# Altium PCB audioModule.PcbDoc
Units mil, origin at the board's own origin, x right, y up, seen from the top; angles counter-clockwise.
Board outline 1259.84 x 708.66 mil, 2 copper layers (Top Layer, Bottom Layer); 25 components, 25 nets, 91 pads, 34 vias.
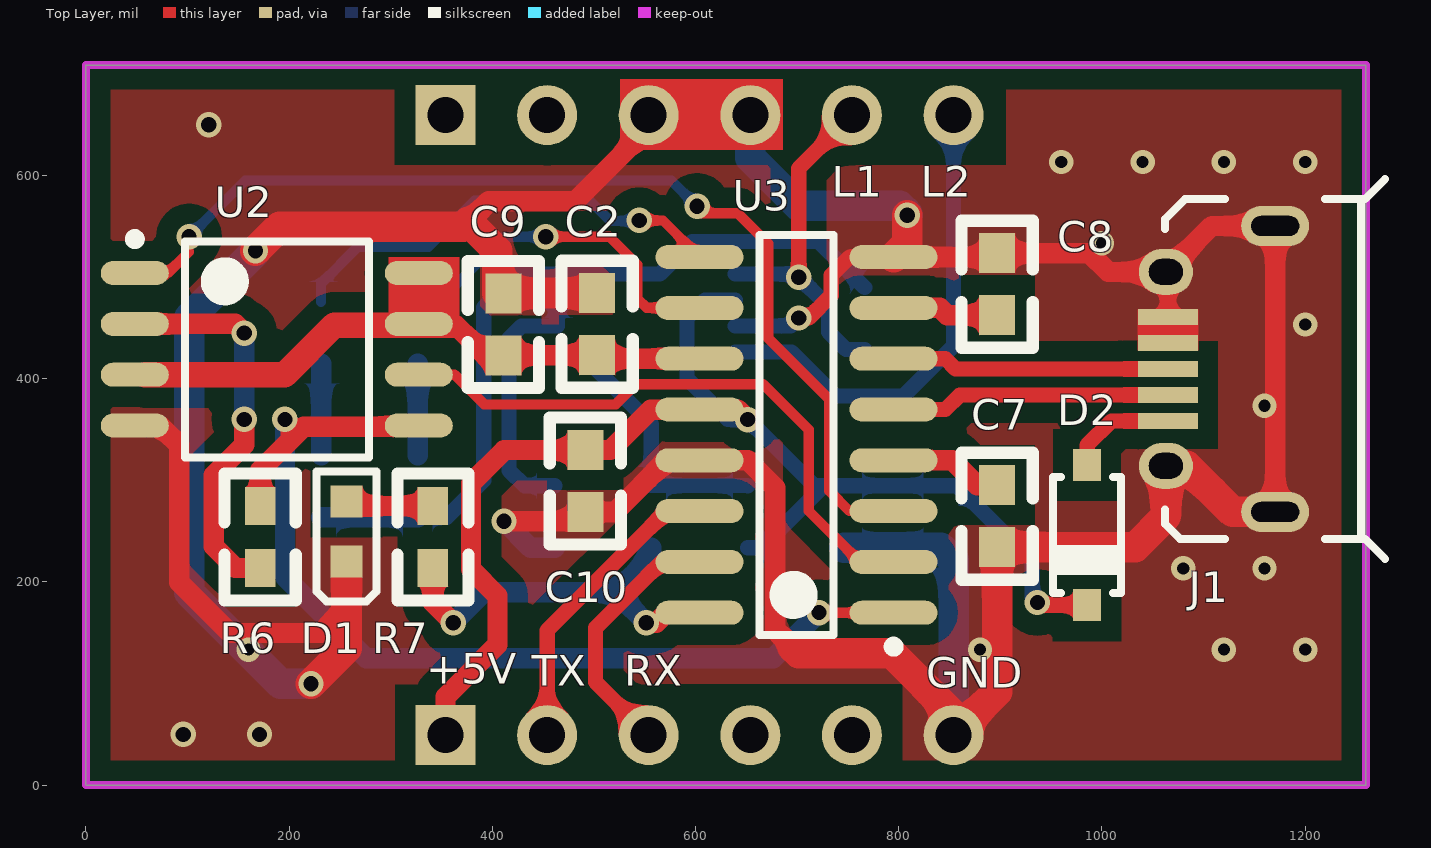
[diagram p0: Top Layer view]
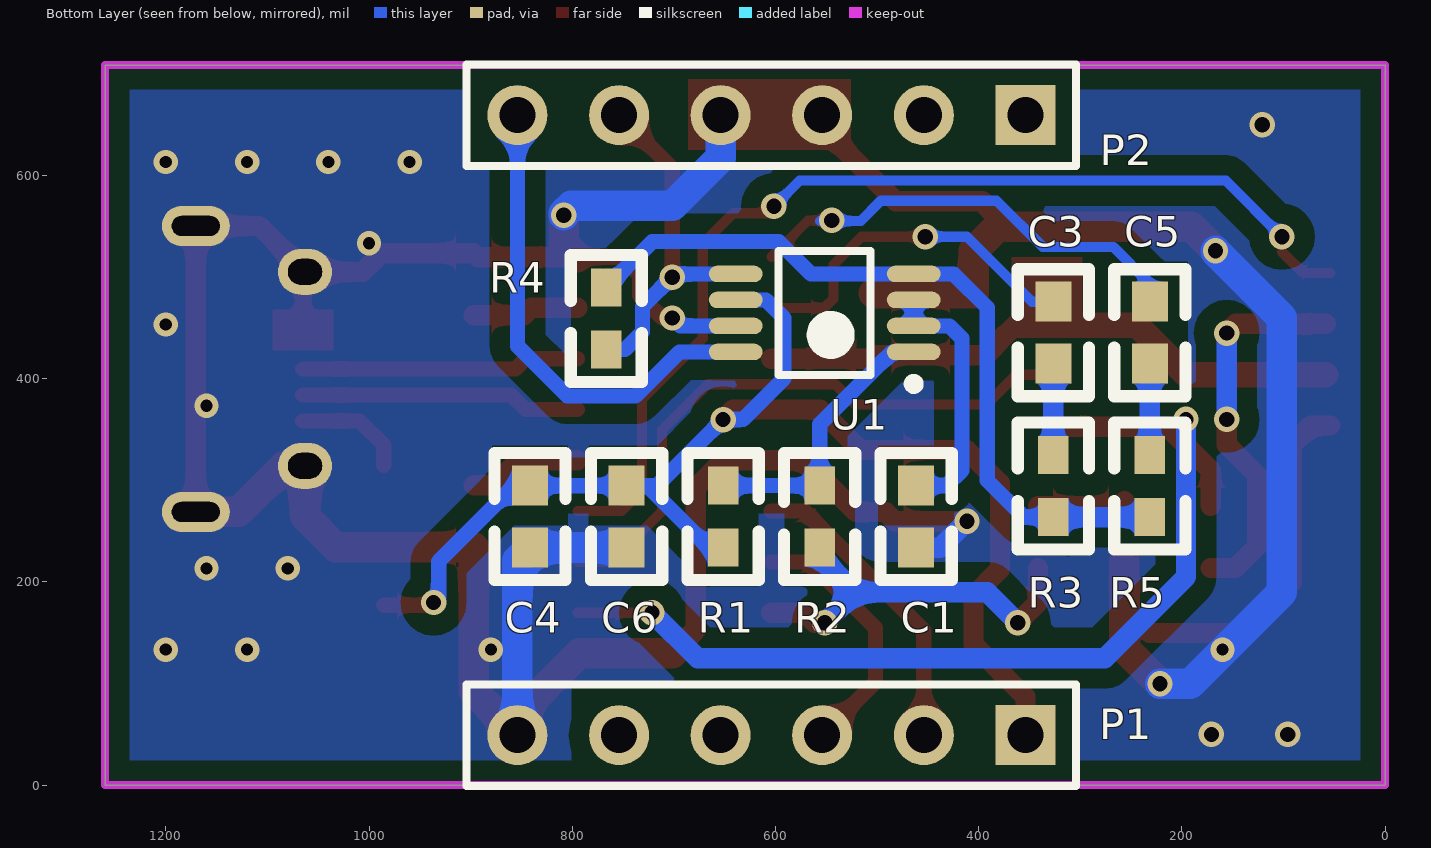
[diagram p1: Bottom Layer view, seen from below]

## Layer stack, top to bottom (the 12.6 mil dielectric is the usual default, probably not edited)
Top Solder: solder mask 0.4, Solder Resist, Dk 3.5
Top Layer: signal copper 1.4
Dielectric 1: dielectric 12.6, FR-4, Dk 4.8
Bottom Layer: signal copper 1.4
Bottom Solder: solder mask 0.4, Solder Resist, Dk 3.5

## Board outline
0,0 1259.84,0 1259.84,708.66 0,708.66

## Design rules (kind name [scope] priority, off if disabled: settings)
Clearance Clearance_2 [InPolygon] p1: gap=20
Clearance Clearance_1 [All] p2: gap=8
Clearance [All] p3: gap=10
DiffPairsRouting [All] p1: maxlimit=10 minlimit=10 mostfreqgap=10 toplayer_minwidth=15 toplayer_maxwidth=15 toplayer_prefwidth=15 bottomlayer_minwidth=15 bottomlayer_maxwidth=15 bottomlayer_prefwidth=15 maxuncoupledlength=500
MinimumSolderMaskSliver [All] p1 off: minsoldermaskwidth=10
PlaneConnect [All] p1: planeconnectstyle=Direct reliefexpansion=20 reliefentries=4 reliefconductorwidth=10 reliefairgap=10
PolygonConnect [All] p1: connectstyle=Direct reliefconductorwidth=10 reliefentries=4 polygonreliefangle="90 Angle" airgapwidth=10
RoutingVias RoutingVias_1 [All] p1: holewidth=28 width=50 viastyle="Through Hole" minholewidth=10 minwidth=25 maxholewidth=28 maxwidth=50
RoutingVias [All] p2: holewidth=28 width=50 viastyle="Through Hole" minholewidth=28 minwidth=50 maxholewidth=28 maxwidth=50
SilkToSolderMaskClearance [IsPad] p1: minsilkscreentomaskgap=5 clearancetoexposedcopper=TRUE
SolderMaskExpansion [All] p1: expansion=4
Width Width_1 [All] p1: maxlimit=50 minlimit=10 preferedwidth=10
Width [All] p2: maxlimit=10 minlimit=10 preferedwidth=10
26 further rules are at their usual default settings.

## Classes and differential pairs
differential pair USB: +USB_P -USB_N

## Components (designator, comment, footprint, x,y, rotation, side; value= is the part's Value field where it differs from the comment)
C1 "Cap Semi" B0603C 461.63,233.79 r90 bottom
C2 "Cap Semi" B0603C 503.28,423.23 r90 top
C3 "Cap Semi" B0603C 326.63,414.84 r90 bottom
C4 "Cap Semi" B0603C 841.63,233.79 r90 bottom
C5 "Cap Semi" B0603C 231.63,414.84 r90 bottom
C6 "Cap Semi" B0603C 746.63,233.79 r90 bottom
C7 "Cap Semi" B0603C 896.98,234.25 r90 top
C8 "Cap Semi" B0603C 896.98,523.62 r270 top
C9 "Cap Semi" B0603C 411,484.02 r270 top
C10 "Cap Semi" B0603C 491.63,268.82 r90 top
D1 "LED" LED_0603 256.63,249.84 r270 top
D2 "1N4148W-SOD123" SOD123 985.57,246.06 r270 top
J1 "USB Micro" USB2.0-MICRO-TYPEB-03 1170.63,409.69 r90 top
P1 "Header 6" HDR1X6 354.07,49.21 r0 bottom
P2 "Header 6" HDR1X6 354.07,659.45 r0 bottom
R1 "Res Semi" B0603R 651.63,294.82 r270 bottom
R2 "Res Semi" B0603R 556.63,233.82 r90 bottom
R3 "Res Semi" B0603R 326.63,324.82 r270 bottom
R4 "Res Semi" B0603R 766.63,489.82 r270 bottom
R5 "Res Semi" B0603R 231.63,324.82 r270 bottom
R6 "Res Semi" B0603R 171.63,213.82 r90 top
R7 "Res Semi" B0603R 341.63,213.82 r90 top
U1 "XPT4890-MSOP8" XPT4890MS-MSOP8 551.63,464.84 r0 bottom
U2 "W25Q16" SOIC127P790X216-8N 188,429 r0 top
U3 "CX800D-SOP16" SOP16N 699.62,344.76 r180 top

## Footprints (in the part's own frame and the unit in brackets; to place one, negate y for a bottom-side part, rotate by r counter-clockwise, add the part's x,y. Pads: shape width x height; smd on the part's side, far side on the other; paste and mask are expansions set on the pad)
B0603C [mm]
  rect 1x0.9 smd: 1(1.55,0) 2(0,0)
  silkscreen extent -0.81,-0.89 2.36,0.89
B0603R [mm]
  rect 0.95x0.762 smd: 1(0,0) 2(1.55,0)
  silkscreen extent -0.81,-0.89 2.36,0.89
HDR1X6 [mm] "Connector; Header; 6 Position"
  rect 1.5x1.5 hole 0.9: 1(0,0)
  round 1.5 hole 0.9: 2(2.54,0) 3(5.08,0) 4(7.62,0) 5(10.16,0) 6(12.7,0)
  silkscreen extent -1.27,-1.27 13.97,1.27
LED_0603 [mm]
  rect 0.8x0.8 smd: A(-0.75,0) K(0.75,0)
  silkscreen extent -1.5,-0.75 1.75,0.75
SOD123 [mm] "SODFL, 2-Leads, Body 1.55x3.70mm, IPC Medium Density"
  rect 0.8x0.7 smd: A(-1.75,0) K(1.75,0)
  silkscreen extent -1.45,-0.85 1.45,0.85, body extent -1.42,-0.85 1.43,0.85, height 1.35
SOIC127P790X216-8N [mm] "SOIC, 8-Leads, Body 5.28x5.28mm, Pitch 1.27mm, IPC Medium Density"
  oval 1.7x0.6 smd: 1(-3.55,1.905) 2(-3.55,0.635) 3(-3.55,-0.635) 4(-3.55,-1.905) 5(3.55,-1.905) 6(3.55,-0.635) 7(3.55,0.635) 8(3.55,1.905)
  silkscreen extent -3.67,-2.7 2.3,2.88, body extent -2.7,-2.7 2.7,2.7, height 2.16
SOP16N [mm] "SOP, 16-Leads, Body 10.0x4.0mm (max), Pitch 1.27mm, IPC Medium Density"
  oval 2.2x0.6 smd: 1(-2.425,4.445) 2(-2.425,3.175) 3(-2.425,1.905) 4(-2.425,0.635) 5(-2.425,-0.635) 6(-2.425,-1.905) 7(-2.425,-3.175) 8(-2.425,-4.445) 9(2.425,-4.445) 10(2.425,-3.175) 11(2.425,-1.905) 12(2.425,-0.635) 13(2.425,0.635) 14(2.425,1.905) 15(2.425,3.175) 16(2.425,4.445)
  silkscreen extent -2.55,-5 0.93,5.42, body extent -2,-5 2,5, height 1.75
USB2.0-MICRO-TYPEB-03 [mm] "4 insertion feet"
  rect 0.4x1.5 smd: 1(-1.3,2.675) 2(-0.65,2.675) 3(0,2.675) 4(0.65,2.675) 5(1.3,2.675)
  oval 1x1.7 hole 0.5 slot 1.2 at 90 deg: S(-3.575,0) S(3.575,0)
  oval 1.15x1.35 hole 0.65 slot 0.85 at 90 deg: S(-2.425,2.73) S(2.425,2.73)
  silkscreen extent -4.75,-2.75 4.75,2.75
XPT4890MS-MSOP8 [mm] "TSOP, 8-Leads, Body 3.00x3.00mm, Pitch 0.65mm, IPC Medium Density"
  oval 1.35x0.41 smd: 1(-2.225,0.975) 2(-2.225,0.325) 3(-2.225,-0.325) 4(-2.225,-0.975) 5(2.225,-0.975) 6(2.225,-0.325) 7(2.225,0.325) 8(2.225,0.975)
  silkscreen extent -2.35,-1.55 1.15,1.9, body extent -1.55,-1.55 1.55,1.55, height 1.09

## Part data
C1 C2 C3 C4 C5 C6 C7 C8 C9 C10: "Capacitor (Semiconductor SIM Model)"
D2: library part 1N5822, "Diode"
J1: library part "USB 2.0 Type B Micro"
P1 P2: "Header, 6-Pin"
R1 R2 R3 R4 R5 R6 R7: "Semiconductor Resistor"
U1: library part XPT4890, "AudioPowerAmplifierIC"
U3: library part CX800D, "AudioIC"

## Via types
v1: diameter 25, hole 15, Top Layer to Bottom Layer, 21 vias
v2: diameter 24, hole 12, Top Layer to Bottom Layer, 13 vias

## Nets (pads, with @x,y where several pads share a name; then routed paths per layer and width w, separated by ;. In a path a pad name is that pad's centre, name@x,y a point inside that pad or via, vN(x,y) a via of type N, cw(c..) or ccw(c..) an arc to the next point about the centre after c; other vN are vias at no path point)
AL: C5.1 U3.9 | length 470.5
  Top Layer w10: v1(544.63,555.84) 568.07,555.84 U3.9
  Bottom Layer w10: C5.1 231.63,493.84 267.63,529.84 337.17,529.84 382.49,575.16 496.31,575.16 516.13,555.34 556.13,555.34 555.63,555.84 v1(544.63,555.84)
AR: C3.1 U3.10 | length 352.7
  Top Layer w10: v1(452.63,539.84) 515.42,539.84 542.97,512.29 542.97,478.81 552.02,469.76 U3.10
  Bottom Layer w10: C3.1 347.65,475.87 411.63,539.84 v1(452.63,539.84)
BUSY: R2.1 R7.1 U3.16 | length 392.2
  Top Layer w20: R7.1 341.63,179.84 v1(361.63,159.84) ; v1(551.63,159.84) 561.63,159.84 571.55,169.76 U3.16
  Bottom Layer w20: v1(361.63,159.84) 391.63,189.84 521.63,189.84 ; v1(551.63,159.84) 521.63,189.84 ; R2.1 556.63,224.84 521.63,189.84
GND: C1.2 C2.1 C4.2 C6.2 C7.2 C8.2 C9.2 C10.2 D1.K J1.4 J1.5 J1.S P1.6 P2.3 P2.4 U1.7 U2.4 U3.8 U3.13 | length 4550.5
  Top Layer w15: v1(701.63,459.84) 711.63,459.84 733.63,481.84 733.63,501.84 751.55,519.76 U3.8 ; J1.S@1063.15,505.16 1065.31,502.99 J1.5 J1.4
  Top Layer w20: U2.4@54,354 73,354 91.87,335.13 91.87,199.61 141.63,149.84 231.63,149.84 256.63,174.84 ; 376.39,554.61 396.63,574.84 481.63,574.84 554.07,647.28 P2.3 P2.4 ; v1(411.63,259.84) 482.65,259.84 C10.2 520.61,268.82 571.55,319.76 U3.13 651.71,319.76 678.63,292.84 678.63,152.84 695.13,136.34 ; U3.8 893.13,519.76 C8.2 987.85,523.62 1006.31,505.16 1063.15,505.16 1108.43,550.43 1170.63,550.43 J1.S@1170.63,268.94
  Top Layer w30: v1(167,526) 190.84,549.84 371.63,549.84 ; v1(221.63,99.84) 256.63,134.84 256.63,174.84 D1.K ; 376.39,554.61 404.86,526.14 C9.2@404.86,484.28 ; C9.2@404.88,484.25 C2.1 ; 695.13,136.34 701.63,129.84 793.13,129.84 854.07,68.9 P1.6 896.98,92.13 C7.2 1032.81,234.25 1063.15,264.59 1063.15,314.21 1083.43,314.21 1128.7,268.94 J1.S@1170.63,268.94 ; U3.8 808.4,533.07 v1(808.4,561.02)
  Bottom Layer w15: U1.7 693.83,452.05 v1(701.63,459.84)
  Bottom Layer w20: v1(411.63,259.84) 437.68,233.79 C1.2
  Bottom Layer w30: v1(167,526) 167,525.21 101.63,459.84 101.63,189.84 191.63,99.84 v1(221.63,99.84) ; P2.4 654.07,617.72 701.44,570.34 801.13,570.34 808.4,563.07 v1(808.4,561.02) ; C6.2 C4.2 854.07,221.35 P1.6
  other v1: 96,50 171,50 121,650
  other v2: 160.16,133.39 880.16,133.39 1120.16,133.39 1200.16,133.39 1080.16,213.39 1160.16,213.39 1160.16,373.39 1200.16,453.39 1000.16,533.39 960.16,613.39 1040.16,613.39 1120.16,613.39 1200.16,613.39
L1: P2.5 R4.2 U1.5 | length 354.3
  Top Layer w15: v1(701.63,499.84) 701.63,607.01 P2.5
  Bottom Layer w15: U1.5 698.24,503.23 v1(701.63,499.84) 702.29,499.84 731,471.13 731,446 748.21,428.79 R4.2
L2: P2.6 U1.8 | length 480.5
  Bottom Layer w15: U1.8 694.54,426.46 738,383 805,383 854.07,432.07 P2.6
NetC1_1: C1.1 U1.2 U1.3 | length 259.3
  Bottom Layer w15: C1.1 431.65,294.82 416.63,309.84 416.63,439.84 428.83,452.05 U1.2 U1.3
NetC3_2: C3.2 R3.1 | length 90
  Bottom Layer w20: R3.1 C3.2
NetC5_2: C5.2 R5.1 | length 90
  Bottom Layer w20: R5.1 C5.2
NetC7_1: C7.1 U3.4 | length 112
  Top Layer w20: U3.4 852.81,319.76 877.3,295.28 C7.1
NetC8_1: C8.1 U3.7 | length 104.9
  Top Layer w20: U3.7 840.61,469.76 847.77,462.6 C8.1
NetD1_A: D1.A R7.2 | length 86.9
  Top Layer w20: D1.A 261.16,274.84 R7.2
NetD2_A: D2.A J1.1 | length 109.3
  Top Layer w15: D2.A 985.57,334.65 1009.43,358.5 J1.1
NetR1_1: R1.1 R2.2 U1.1 | length 277.5
  Bottom Layer w15: U1.1 485.33,426.46 556.63,355.16 R2.2 R1.1@651.61,294.84
NetR3_2: R3.2 R4.1 R5.2 U1.4 | length 766
  Bottom Layer w15: R3.2 355.58,263.79 391.63,299.84 391.63,470.16 424.7,503.23 U1.4 565.02,503.23 596.94,535.16 721.29,535.16 R4.1
  Bottom Layer w20: R5.2 R3.2
NetR6_1: R6.1 U2.2 | length 378.3
  Top Layer w20: U2.2@58.24,454 147,454 v1(156,445) ; v1(156,360) 156,335 126,305 126,235 147.18,213.82 R6.1
  Bottom Layer w20: v1(156,360) v1(156,445)
RXD: P1.3 U3.15 | length 278.3
  Top Layer w15: P1.3@532.57,49.21 P1.3 501.63,101.65 501.63,154.84 566.55,219.76 U3.15
SPI-CLK: U2.6 U3.2 | length 618.5
  Top Layer w10: U2.6@316.28,402.76 U2.6@337.76,402.76 ; U2.6@337.76,404 363,404 392.16,374.84 521.63,374.84 541.36,394.57 666.63,394.57 711.05,350.16 711.63,350.16 711.63,269.84 761.71,219.76 U3.2
SPI-CS: U2.1 U3.3 | length 1014.7
  Top Layer w10: U2.1@54,504 80.63,504 101.63,525 ; v1(601.63,569.84) 608.63,562.84 641.63,562.84 671.63,532.84 671.63,439.84 731.63,379.84 731.63,289.84 751.71,269.76 U3.3
  Bottom Layer w10: v1(101.63,539.84) 156.94,595.16 576.31,595.16 v1(601.63,569.84)
SPI-DAT: R6.2 U2.5 U3.1 | length 1025.7
  Top Layer w10: v1(721.63,169.84) 731.63,169.84 731.71,169.76 U3.1
  Top Layer w20: R6.2 171.63,309.84 201.79,340 ; v1(196,360) 201.79,354.21 201.79,340 ; U2.5@316.28,352.76 214.54,352.76 201.79,340
  Bottom Layer w20: v1(196,360) 196,205 276,125 676.79,125 v1(721.63,169.84)
TXD: P1.2 U3.14 | length 301.8
  Top Layer w15: P1.2 454.07,152.28 571.55,269.76 U3.14
USB_N: J1.2 U3.5 | length 276.2
  Top Layer w15: U3.5 845.9,369.76 860.23,384.09 J1.2
USB_P: J1.3 U3.6 | length 274.4
  Top Layer w15: U3.6 845.9,419.76 855.98,409.69 J1.3
VCC_5V: C4.1 C6.1 C10.1 D2.K P1.1 R1.2 U1.6 U3.12 | length 1308.5
  Top Layer w15: v1(936.63,179.84) 939.31,177.17 D2.K
  Top Layer w20: P1.1 354.07,87.01 405.13,138.07 405.13,186.34 379.13,212.34 379.13,297.34 411.63,329.84 C10.1 516.31,329.84 556.05,369.57 U3.12@566.55,369.57 ; U3.12@566.55,369.76 U3.12 641.71,369.76 v1(651.63,359.84)
  Bottom Layer w15: U1.6 609.43,477.64 591.63,459.84 591.63,400.16 631.94,359.84 v1(651.63,359.84) 716.65,294.82 726.61,294.82 ; R1.2 665.58,233.79 726.61,294.82 ; v1(936.63,179.84) 931.63,184.84 931.63,220.16 856.97,294.82 C4.1 C6.1 726.61,294.82
VOUT_3V3: C2.2 C9.1 U2.3 U2.7 U2.8 U3.11 | length 587.3
  Top Layer w20: U2.7@316.28,452.76 U2.7@337.76,452.76 ; U2.7@337.76,454 U2.7@337.76,452.76 ; C9.1@404.88,423.23 C2.2 506.75,419.76 U3.11 ; C9.1 394,423 364.24,452.76 U2.7@337.76,452.76
  Top Layer w25: U2.3@58.24,404 195.79,404 244.54,452.76 U2.7@316.28,452.76
pads on no net: P1.4 P1.5 P2.1 P2.2

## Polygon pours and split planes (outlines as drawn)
GND on Top Layer "Bottom Layer-No Net" (solid, remove dead copper, pour order 2): 0,708.66 0,0 1259.84,0 1259.84,708.66 0,708.66
GND on Bottom Layer "Bottom Layer-No Net" (solid, remove dead copper, pour order 4): 0,708.66 0,0 1259.84,0 1259.84,708.66 0,708.66

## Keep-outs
Keep-Out Layer:
  the board outline again, w7.87

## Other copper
Top Layer:
  rectangle net GND: 1035,428 1095,468
  rectangle net VOUT_3V3: 298,440 368,520
  rectangle net GND: 526,625 686,695
  pour cut-out: 303.5,610 906,610 906,710 303.5,710
  pour cut-out: 304.07,-0.83 804.07,-0.83 804.07,99.17 304.07,99.17
Bottom Layer:
  pour cut-out: 301,0 801,0 801,100 301,100
  pour cut-out: 306,708.66 306,610 906,610 906,708.66

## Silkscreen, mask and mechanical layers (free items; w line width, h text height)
Top Overlay:
  text "L1" at 734,579 h30
  text "L2" at 822,579 h30
  text "+5V" at 335,100 h30
  text "TX" at 439,98 h30
  text "RX" at 530,98 h30
  text "GND" at 827,95.97 h30
Mechanical 1:
  lines w7.87: 0,705 0,0 1260,0 1260,708.5 0.16,708.5
Drill Drawing:
  text ".Legend" at -12,819 h30

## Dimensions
0,0 to 1259.84,0 on Mechanical 1
0,708.66 to 0,0 on Mechanical 1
